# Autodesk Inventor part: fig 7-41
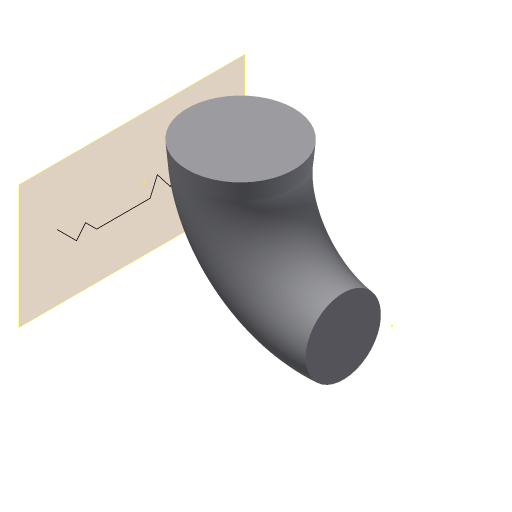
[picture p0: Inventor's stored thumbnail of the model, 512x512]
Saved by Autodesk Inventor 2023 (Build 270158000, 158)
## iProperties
Created: 2011-07
Part Number: fig 7-41
Material: Generic
Document SubType Name: Modeling
Designer: CadCim
Density: 1 g/cm^3
Appearance: Default
Author: CadCim
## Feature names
1. Sweep1
## Parameters: d0 = 5 deg, d1 = -14.75 mm, d2 = 0
